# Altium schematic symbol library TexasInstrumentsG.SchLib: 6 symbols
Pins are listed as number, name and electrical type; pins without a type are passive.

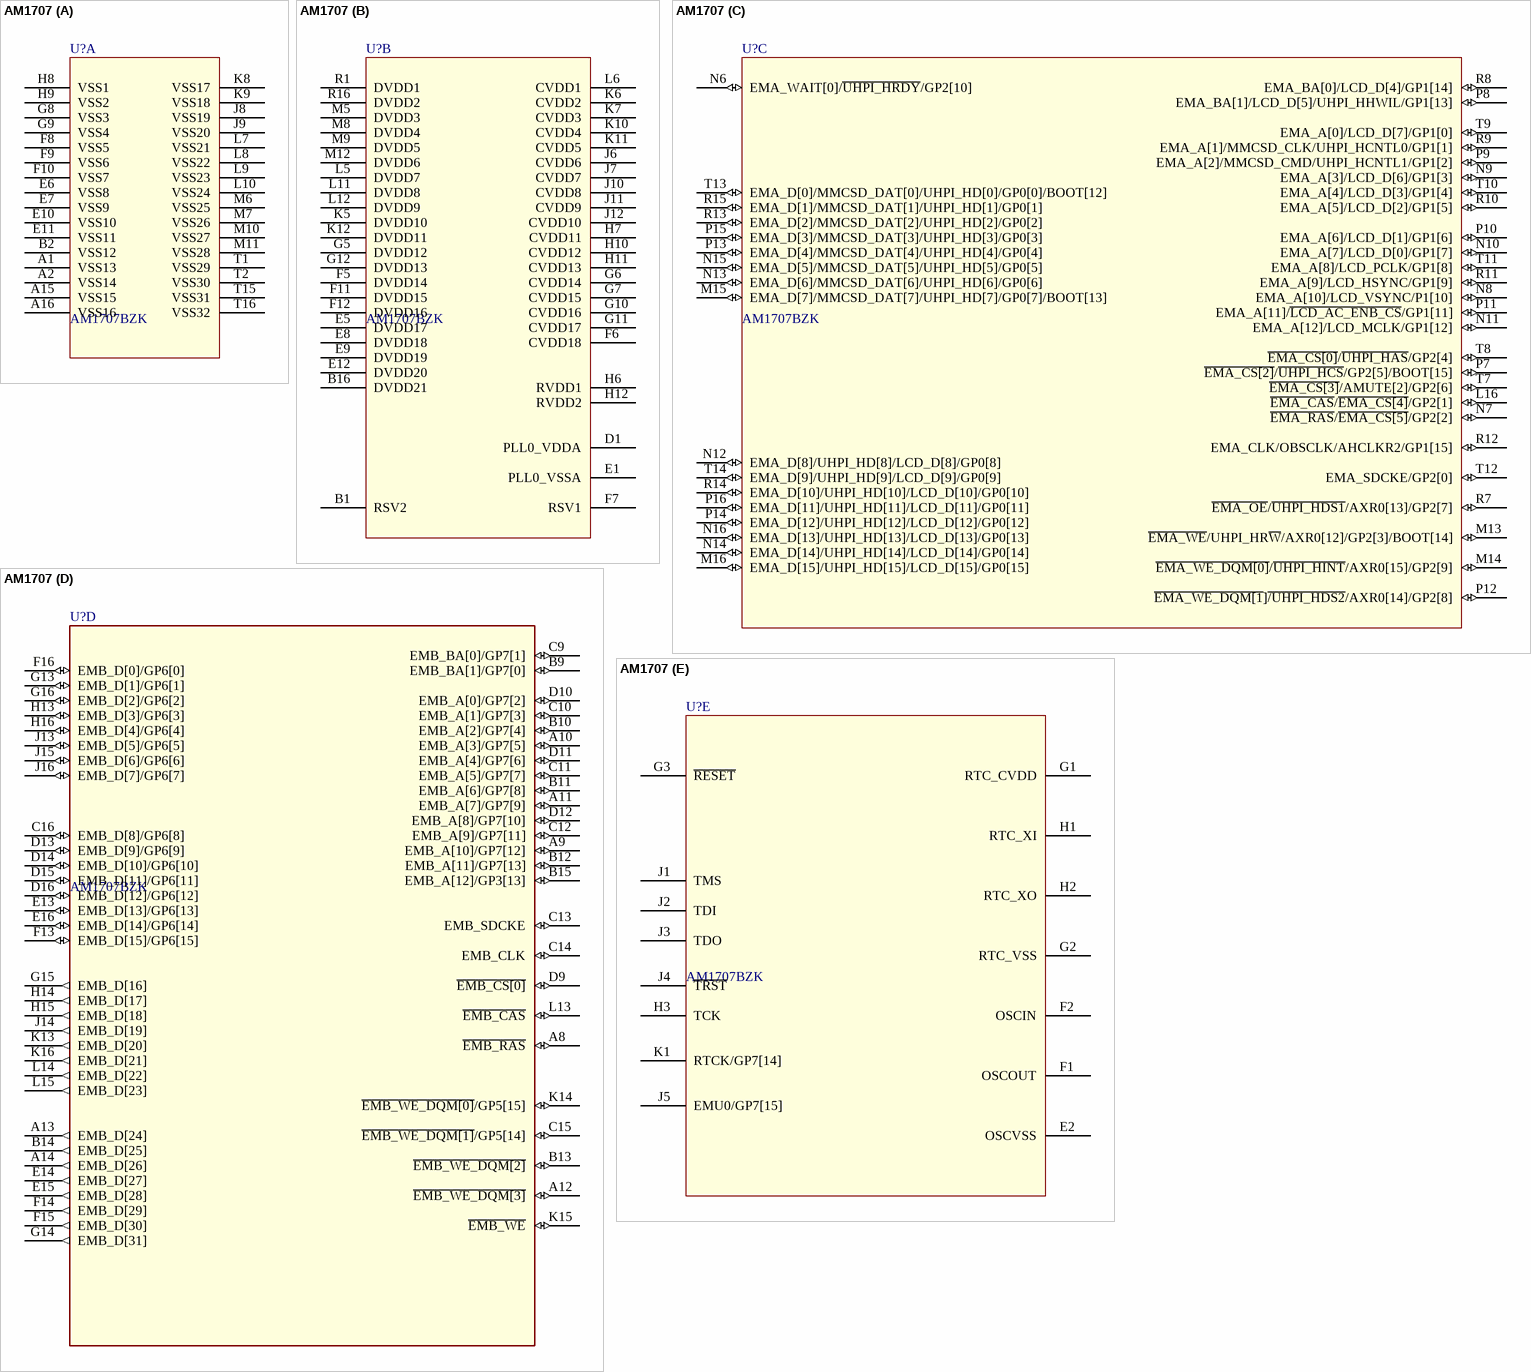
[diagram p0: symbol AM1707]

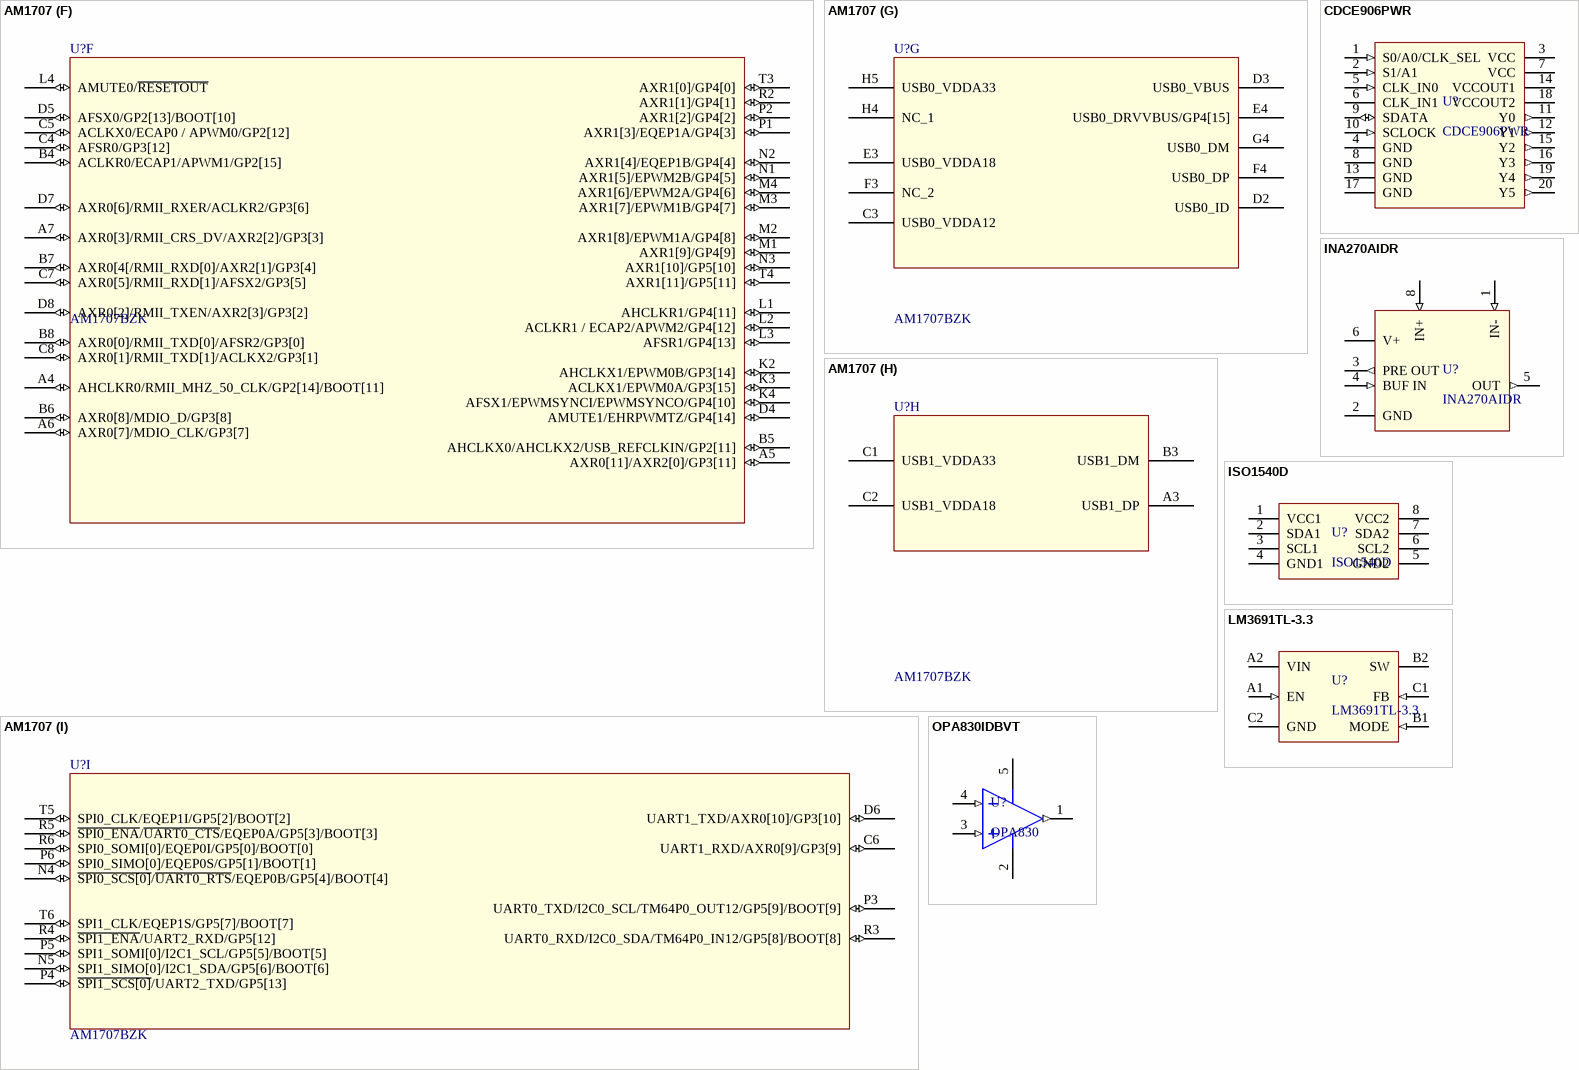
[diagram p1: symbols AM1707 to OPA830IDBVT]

## AM1707
designator U?, comment AM1707BZK
footprint C6747
part A pins: A1 VSS13 (power), A2 VSS14 (power), A15 VSS15 (power), A16 VSS16 (power), B2 VSS12 (power), E6 VSS8 (power), E7 VSS9 (power), E10 VSS10 (power), E11 VSS11 (power), F8 VSS5 (power), F9 VSS6 (power), F10 VSS7 (power), G8 VSS3 (power), G9 VSS4 (power), H8 VSS1 (power), H9 VSS2 (power), J8 VSS19 (power), J9 VSS20 (power), K8 VSS17 (power), K9 VSS18 (power), L7 VSS21 (power), L8 VSS22 (power), L9 VSS23 (power), L10 VSS24 (power), M6 VSS25 (power), M7 VSS26 (power), M10 VSS27 (power), M11 VSS28 (power), T1 VSS29 (power), T2 VSS30 (power), T15 VSS31 (power), T16 VSS32 (power)
part B pins: B1 RSV2, B16 DVDD21 (power), D1 PLL0_VDDA, E1 PLL0_VSSA, E5 DVDD17 (power), E8 DVDD18 (power), E9 DVDD19 (power), E12 DVDD20 (power), F5 DVDD14 (power), F6 CVDD18 (power), F7 RSV1, F11 DVDD15 (power), F12 DVDD16 (power), G5 DVDD12 (power), G6 CVDD14 (power), G7 CVDD15 (power), G10 CVDD16 (power), G11 CVDD17 (power), G12 DVDD13 (power), H6 RVDD1 (power), H7 CVDD11 (power), H10 CVDD12 (power), H11 CVDD13 (power), H12 RVDD2 (power), J6 CVDD6 (power), J7 CVDD7 (power), J10 CVDD8 (power), J11 CVDD9 (power), J12 CVDD10 (power), K5 DVDD10 (power), K6 CVDD2 (power), K7 CVDD3 (power), K10 CVDD4 (power), K11 CVDD5 (power), K12 DVDD11 (power), L5 DVDD7 (power), L6 CVDD1 (power), L11 DVDD8 (power), L12 DVDD9 (power), M5 DVDD3 (power), M8 DVDD4 (power), M9 DVDD5 (power), M12 DVDD6 (power), R1 DVDD1 (power), R16 DVDD2 (power)
part C pins: L16 ~{EMA_CAS}/~{EMA_CS[4]}/GP2[1] (io), M13 ~{EMA_WE}/UHPI_HR~{W}/AXR0[12]/GP2[3]/BOOT[14] (io), M14 ~{EMA_WE_DQM[0]}/~{UHPI_HINT}/AXR0[15]/GP2[9] (io), M15 EMA_D[7]/MMCSD_DAT[7]/UHPI_HD[7]/GP0[7]/BOOT[13] (io), M16 EMA_D[15]/UHPI_HD[15]/LCD_D[15]/GP0[15] (io), N6 EMA_WAIT[0]/~{UHPI_HRDY}/GP2[10] (io), N7 ~{EMA_RAS}/~{EMA_CS[5]}/GP2[2] (io), N8 EMA_A[10]/LCD_VSYNC/P1[10] (io), N9 EMA_A[3]/LCD_D[6]/GP1[3] (io), N10 EMA_A[7]/LCD_D[0]/GP1[7] (io), N11 EMA_A[12]/LCD_MCLK/GP1[12] (io), N12 EMA_D[8]/UHPI_HD[8]/LCD_D[8]/GP0[8] (io), N13 EMA_D[6]/MMCSD_DAT[6]/UHPI_HD[6]/GP0[6] (io), N14 EMA_D[14]/UHPI_HD[14]/LCD_D[14]/GP0[14] (io), N15 EMA_D[5]/MMCSD_DAT[5]/UHPI_HD[5]/GP0[5] (io), N16 EMA_D[13]/UHPI_HD[13]/LCD_D[13]/GP0[13] (io), P7 ~{EMA_CS[2]}/~{UHPI_HCS}/GP2[5]/BOOT[15] (io), P8 EMA_BA[1]/LCD_D[5]/UHPI_HHWIL/GP1[13] (io), P9 EMA_A[2]/MMCSD_CMD/UHPI_HCNTL1/GP1[2] (io), P10 EMA_A[6]/LCD_D[1]/GP1[6] (io), P11 EMA_A[11]/~{LCD_AC_ENB_CS}/GP1[11] (io), P12 ~{EMA_WE_DQM[1}]~{/UHPI_HDS2}/AXR0[14]/GP2[8] (io), P13 EMA_D[4]/MMCSD_DAT[4]/UHPI_HD[4]/GP0[4] (io), P14 EMA_D[12]/UHPI_HD[12]/LCD_D[12]/GP0[12] (io), P15 EMA_D[3]/MMCSD_DAT[3]/UHPI_HD[3]/GP0[3] (io), P16 EMA_D[11]/UHPI_HD[11]/LCD_D[11]/GP0[11] (io), R7 ~{EMA_OE}/~{UHPI_HDS1}/AXR0[13]/GP2[7] (io), R8 EMA_BA[0]/LCD_D[4]/GP1[14] (io), R9 EMA_A[1]/MMCSD_CLK/UHPI_HCNTL0/GP1[1] (io), R10 EMA_A[5]/LCD_D[2]/GP1[5] (io), R11 EMA_A[9]/LCD_HSYNC/GP1[9] (io), R12 EMA_CLK/OBSCLK/AHCLKR2/GP1[15] (io), R13 EMA_D[2]/MMCSD_DAT[2]/UHPI_HD[2]/GP0[2] (io), R14 EMA_D[10]/UHPI_HD[10]/LCD_D[10]/GP0[10] (io), R15 EMA_D[1]/MMCSD_DAT[1]/UHPI_HD[1]/GP0[1] (io), T7 ~{EMA_CS[3]}/AMUTE[2]/GP2[6] (io), T8 ~{EMA_CS[0]}/~{UHPI_HAS}/GP2[4] (io), T9 EMA_A[0]/LCD_D[7]/GP1[0] (io), T10 EMA_A[4]/LCD_D[3]/GP1[4] (io), T11 EMA_A[8]/LCD_PCLK/GP1[8] (io), T12 EMA_SDCKE/GP2[0] (io), T13 EMA_D[0]/MMCSD_DAT[0]/UHPI_HD[0]/GP0[0]/BOOT[12] (io), T14 EMA_D[9]/UHPI_HD[9]/LCD_D[9]/GP0[9] (io)
part D pins: A8 ~{EMB_RAS} (io), A9 EMB_A[10]/GP7[12] (io), A10 EMB_A[3]/GP7[5] (io), A11 EMB_A[7]/GP7[9] (io), A12 ~{EMB_WE_DQM[3]} (io), A13 EMB_D[24] (out), A14 EMB_D[26] (out), B9 EMB_BA[1]/GP7[0] (io), B10 EMB_A[2]/GP7[4] (io), B11 EMB_A[6]/GP7[8] (io), B12 EMB_A[11]/GP7[13] (io), B13 ~{EMB_WE_DQM[2]} (io), B14 EMB_D[25] (out), B15 EMB_A[12]/GP3[13] (io), C9 EMB_BA[0]/GP7[1] (io), C10 EMB_A[1]/GP7[3] (io), C11 EMB_A[5]/GP7[7] (io), C12 EMB_A[9]/GP7[11] (io), C13 EMB_SDCKE (io), C14 EMB_CLK (io), C15 ~{EMB_WE_DQM[1]}/GP5[14] (io), C16 EMB_D[8]/GP6[8] (io), D9 ~{EMB_CS[0]} (io), D10 EMB_A[0]/GP7[2] (io), D11 EMB_A[4]/GP7[6] (io), D12 EMB_A[8]/GP7[10] (io), D13 EMB_D[9]/GP6[9] (io), D14 EMB_D[10]/GP6[10] (io), D15 EMB_D[11]/GP6[11] (io), D16 EMB_D[12]/GP6[12] (io), E13 EMB_D[13]/GP6[13] (io), E14 EMB_D[27] (out), E15 EMB_D[28] (out), E16 EMB_D[14]/GP6[14] (io), F13 EMB_D[15]/GP6[15] (io), F14 EMB_D[29] (out), F15 EMB_D[30] (out), F16 EMB_D[0]/GP6[0] (io), G13 EMB_D[1]/GP6[1] (io), G14 EMB_D[31] (out), G15 EMB_D[16] (out), G16 EMB_D[2]/GP6[2] (io), H13 EMB_D[3]/GP6[3] (io), H14 EMB_D[17] (out), H15 EMB_D[18] (out), H16 EMB_D[4]/GP6[4] (io), J13 EMB_D[5]/GP6[5] (io), J14 EMB_D[19] (out), J15 EMB_D[6]/GP6[6] (io), J16 EMB_D[7]/GP6[7] (io), K13 EMB_D[20] (out), K14 ~{EMB_WE_DQM[0]}/GP5[15] (io), K15 ~{EMB_WE} (io), K16 EMB_D[21] (out), L13 ~{EMB_CAS} (io), L14 EMB_D[22] (out), L15 EMB_D[23] (out)
part E pins: E2 OSCVSS, F1 OSCOUT, F2 OSCIN, G1 RTC_CVDD, G2 RTC_VSS, G3 ~{RESET}, H1 RTC_XI, H2 RTC_XO, H3 TCK, J1 TMS, J2 TDI, J3 TDO, J4 ~{TRST}, J5 EMU0/GP7[15], K1 RTCK/GP7[14]
part F pins: A4 AHCLKR0/RMII_MHZ_50_CLK/GP2[14]/BOOT[11] (io), A5 AXR0[11]/AXR2[0]/GP3[11] (io), A6 AXR0[7]/MDIO_CLK/GP3[7] (io), A7 AXR0[3]/RMII_CRS_DV/AXR2[2]/GP3[3] (io), B4 ACLKR0/ECAP1/APWM1/GP2[15] (io), B5 AHCLKX0/AHCLKX2/USB_REFCLKIN/GP2[11] (io), B6 AXR0[8]/MDIO_D/GP3[8] (io), B7 AXR0[4[/RMII_RXD[0]/AXR2[1]/GP3[4] (io), B8 AXR0[0]/RMII_TXD[0]/AFSR2/GP3[0] (io), C4 AFSR0/GP3[12] (io), C5 ACLKX0/ECAP0 / APWM0/GP2[12] (io), C7 AXR0[5]/RMII_RXD[1]/AFSX2/GP3[5] (io), C8 AXR0[1]/RMII_TXD[1]/ACLKX2/GP3[1] (io), D4 AMUTE1/EHRPWMTZ/GP4[14] (io), D5 AFSX0/GP2[13]/BOOT[10] (io), D7 AXR0[6]/RMII_RXER/ACLKR2/GP3[6] (io), D8 AXR0[2]/RMII_TXEN/AXR2[3]/GP3[2] (io), K2 AHCLKX1/EPWM0B/GP3[14] (io), K3 ACLKX1/EPWM0A/GP3[15] (io), K4 AFSX1/EPWMSYNCI/EPWMSYNCO/GP4[10] (io), L1 AHCLKR1/GP4[11] (io), L2 ACLKR1 / ECAP2/APWM2/GP4[12] (io), L3 AFSR1/GP4[13] (io), L4 AMUTE0/~{RESETOUT} (io), M1 AXR1[9]/GP4[9] (io), M2 AXR1[8]/EPWM1A/GP4[8] (io), M3 AXR1[7]/EPWM1B/GP4[7] (io), M4 AXR1[6]/EPWM2A/GP4[6] (io), N1 AXR1[5]/EPWM2B/GP4[5] (io), N2 AXR1[4]/EQEP1B/GP4[4] (io), N3 AXR1[10]/GP5[10] (io), P1 AXR1[3]/EQEP1A/GP4[3] (io), P2 AXR1[2]/GP4[2] (io), R2 AXR1[1]/GP4[1] (io), T3 AXR1[0]/GP4[0] (io), T4 AXR1[11]/GP5[11] (io)
part G pins: C3 USB0_VDDA12, D2 USB0_ID, D3 USB0_VBUS, E3 USB0_VDDA18, E4 USB0_DRVVBUS/GP4[15], F3 NC_2, F4 USB0_DP, G4 USB0_DM, H4 NC_1, H5 USB0_VDDA33
part H pins: A3 USB1_DP, B3 USB1_DM, C1 USB1_VDDA33, C2 USB1_VDDA18
part I pins: C6 UART1_RXD/AXR0[9]/GP3[9] (io), D6 UART1_TXD/AXR0[10]/GP3[10] (io), N4 ~{SPI0_SCS[0]}/~{UART0_RTS}/EQEP0B/GP5[4]/BOOT[4] (io), N5 SPI1_SIMO[0]/I2C1_SDA/GP5[6]/BOOT[6] (io), P3 UART0_TXD/I2C0_SCL/TM64P0_OUT12/GP5[9]/BOOT[9] (io), P4 ~{SPI1_SCS[0]}/UART2_TXD/GP5[13] (io), P5 SPI1_SOMI[0]/I2C1_SCL/GP5[5]/BOOT[5] (io), P6 SPI0_SIMO[0]/EQEP0S/GP5[1]/BOOT[1] (io), R3 UART0_RXD/I2C0_SDA/TM64P0_IN12/GP5[8]/BOOT[8] (io), R4 ~{SPI1_ENA}/UART2_RXD/GP5[12] (io), R5 ~{SPI0_ENA}/~{UART0_CTS}/EQEP0A/GP5[3]/BOOT[3] (io), R6 SPI0_SOMI[0]/EQEP0I/GP5[0]/BOOT[0] (io), T5 SPI0_CLK/EQEP1I/GP5[2]/BOOT[2] (io), T6 SPI1_CLK/EQEP1S/GP5[7]/BOOT[7] (io)

## CDCE906PWR
designator U?
Programmable 3-PLL clock synthesizer
footprint PW020 (Shrink Small Outline; 20 Leads; Body Width 4.4 mm; Pitch 0.65 mm)
pins: 1 S0/A0/CLK_SEL (in), 2 S1/A1 (in), 3 VCC (power), 4 GND (power), 5 CLK_IN0 (in), 6 CLK_IN1, 7 VCC (power), 8 GND (power), 9 SDATA (io), 10 SCLOCK (in), 11 Y0 (out), 12 Y1 (out), 13 GND (power), 14 VCCOUT1 (power), 15 Y2 (out), 16 Y3 (out), 17 GND (power), 18 VCCOUT2 (power), 19 Y4 (out), 20 Y5 (out)

## INA270AIDR
designator U?
Current-shunt monitor
footprint SOIC127P600-8N (SOIC, 8-Leads, Body 4.9x3.9mm, Pitch 1.27mm, IPC Medium Density)
pins: 1 IN- (in), 2 GND (power), 3 PRE OUT (out), 4 BUF IN (in), 5 OUT (out), 6 V+ (power), 8 IN+ (in)

## ISO1540D
designator U?
footprint SO8 (Small Outline; 8 Leads; Body Width 3.9 mm; Pitch 1.27 mm)
pins: 1 VCC1, 2 SDA1, 3 SCL1, 4 GND1, 5 GND2, 6 SCL2, 7 SDA2, 8 VCC2

## LM3691TL-3.3
designator U?
footprint YZR0006 (6-DSBGA)
pins: A1 EN (in), A2 VIN (power), B1 MODE (in), B2 SW, C1 FB (in), C2 GND (power)

## OPA830IDBVT
designator U?, comment OPA830
Wideband operational amplifier
footprint DBV005 (SOT-23/SC-74A; 5 Leads; Body 3 x 3 mm, inc. leads (LxW max))
pins: 1 OUT (out), 2 V- (power), 3 IN+ (in), 4 IN- (in), 5 V+ (power)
